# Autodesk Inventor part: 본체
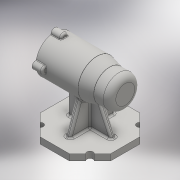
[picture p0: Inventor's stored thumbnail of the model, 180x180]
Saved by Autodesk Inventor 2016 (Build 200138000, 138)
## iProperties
Created: 2019-12
Part Number: 본체
Material: 일반
Document SubType Name: Modeling
Designer: woori
Density: 1 g/cm^3
Appearance: 기본값
Author: woori
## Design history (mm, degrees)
sketch "스케치1"
  geometry: L1 (23.196, 56)-(56, 23.196); L2 (56, 23.196)-(56, -23.196); L3 (56, -23.196)-(23.196, -56); L4 (23.196, -56)-(-23.196, -56); L5 (-23.196, -56)-(-56, -23.196); L6 (-56, -23.196)-(-56, 23.196); L7 (-56, 23.196)-(-23.196, 56); L8 (-23.196, 56)-(23.196, 56); 2 further points
  constraints: 16 end point, 1 coincident, 17 other
  dimensions: "d0" = 56 distance from line of L2 point (0, 0)
extrude "돌출1" new body sketch "스케치1" distance "d1" = 10; taper "d2" = 0 deg
sketch "스케치2"
  geometry: L1 (-56, 80)-(-56, 105); L2 (-56, 105)-(-31, 105); L3 (-31, 105)-(-11, 110); L4 (-11, 110)-(56, 110); L5 (56, 110)-(56, 80); L6 (56, 80)-(-56, 80); L7 (56, 0)-(56, 10) reference; L8 (56, 0)-(23.196, 0) reference; 1 further point
  constraints: 12 end point, 3 perpendicular, 1 collinear, 1 parallel, 1 vertical
  dimensions: "d3" = 45 distance from line of L3.end L1; "d4" = 112 distance between parallel lines of L5 L1; "d5" = 25 distance of L1.end L2.end; "d6" = 60 diameter of L4 L6; "d7" = 50 diameter of L2 L6; "d8" = 80 distance between parallel lines of L8 L6
revolve "회전1" sketch "스케치2" stored, may be unused: angle "d9" = 90 deg
sketch "스케치3"
  geometry: 1 further point
sketch "스케치4"
  geometry: L1 (56, 23.196)-(23.196, 56) reference; L2 (23.196, 56)-(-23.196, 56) reference; L3 (-23.196, 56)-(-56, 23.196) reference; L4 (-56, 23.196)-(-56, -23.196) reference; L5 (-56, -23.196)-(-23.196, -56) reference; L6 (-23.196, -56)-(23.196, -56) reference; L7 (23.196, -56)-(56, -23.196) reference; L8 (56, -23.196)-(56, 23.196) reference; 1 further point
sketch "스케치5"
  geometry: L1 (-23.196, 10)-(-56, 10) reference; L2 (-36, 10)-(-18.979, 56.766); L3 (18.979, 56.766)-(36, 10); L4 (56, 10)-(23.196, 10) reference; L5 (-36, 10)-(36, 10); L6 (23.196, 0)-(56, 0) reference; C1 r 30 at (0, 80); A1 r 30 centre (0, 80) between (-18.979, 56.766) and (18.979, 56.766) reference; 1 further point
  constraints: 6 end point, 2 point on circle, 2 point on line, 1 centre point, 1 coincident, 1 concentric, 1 parallel
  dimensions: "d10" = 20 distance of L1.end L2.start; "d11" = 110 deg angle of L1 L2; "d12" = 20 distance of L4.start L3.end (= d10); "d13" = 110 deg angle of L4 L3
extrude "돌출2" join sketch "스케치5" stored distance "d14" = 8; taper "d15" = 0 deg
sketch "스케치7"
  geometry: L1 (-13.793, 61.912)-(-38, 10); L2 (-56, 10)-(-23.196, 10) reference; L3 (-13.793, 61.912)-(31, 61.912); L4 (31, 61.912)-(31, 10); L5 (23.196, 10)-(56, 10) reference; L6 (-38, 10)-(31, 10); L7 (-23.196, 0)-(23.196, 0) reference; 1 further point
  constraints: 8 end point, 2 point on line, 1 horizontal, 1 parallel, 1 perpendicular
  dimensions: "d21" = 18 distance of L2.start L1.end; "d22" = 25 distance of L5.end L4.end; "d23" = 115 deg angle of L2 L1
extrude "돌출4" join sketch "스케치7" stored distance "d24" = 8; taper "d25" = 0 deg
fillet "모깎기1" dims "d26" = 10
sketch "스케치8"
  geometry: L1 (56, 50)-(56, 110) reference; L2 (56, 80)-(41, 80); L3 (41, 80)-(41, 101); L4 (41, 101)-(56, 101); L5 (56, 101)-(56, 80); L6 (41, 80)-(-13, 80); L7 (-13, 80)-(-13, 104); L8 (-13, 104)-(41, 104); L9 (41, 104)-(41, 80); L10 (-13, 80)-(-25, 80); L11 (-25, 80)-(-25, 101); L12 (-25, 101)-(-13, 101); L13 (-13, 101)-(-13, 80); L14 (-25, 80)-(-43, 80); L15 (-43, 80)-(-43, 97.5); L16 (-43, 97.5)-(-25, 97.5); L17 (-25, 97.5)-(-25, 80); L18 (-43, 80)-(-47, 80); L19 (-47, 80)-(-47, 96); L20 (-47, 96)-(-43, 96); L21 (-43, 96)-(-43, 80); L22 (-47, 80)-(-50, 80); L23 (-50, 80)-(-50, 90.5); L24 (-50, 90.5)-(-47, 90.5); L25 (-47, 90.5)-(-47, 80); 1 further point
  constraints: 48 end point, 12 parallel, 6 horizontal, 6 perpendicular, 1 midpoint
  dimensions: "d27" = 15 distance between parallel lines of L3 L1; "d28" = 54 distance between parallel lines of L3 L13; "d29" = 12 distance between parallel lines of L11 L13; "d30" = 18 distance between parallel lines of L11 L15; "d31" = 3 distance between parallel lines of L19 L23; "d32" = 4 distance between parallel lines of L15 L19; "d33" = 42 diameter of L4 L2; "d34" = 48 diameter of L8 L6; "d35" = 42 diameter of L12 L10; "d36" = 35 diameter of L16 L14; "d37" = 32 diameter of L20 L18; "d38" = 21 diameter of L24 L22
revolve "회전2" sketch "스케치8" stored, may be unused: angle "d39" = 90 deg
fillet "모깎기2" dims "d40" = 0.3
fillet "모깎기3" dims "d41" = 3
fillet "모깎기4" dims "d42" = 3
chamfer "모따기1" distance "d43" = 1; stored, may be unused: second distance "d44" = 2, angle "d45" = 45 deg
sketch "스케치9"
  geometry: L1 (23.196, 56)-(56, 23.196) reference; L2 (56, -23.196)-(23.196, -56) reference; L3 (-23.196, -56)-(-56, -23.196) reference; L4 (-56, 23.196)-(-23.196, 56) reference; C1 r 5 at (39.598, 39.598); C2 r 5 at (39.598, -39.598); C3 r 5 at (-39.598, -39.598); C4 r 5 at (-39.598, 39.598); 2 further points
  constraints: 4 centre point, 4 midpoint, 1 coincident, 3 other
  dimensions: "d46" = 10 diameter of C1; "d47" = 10 diameter of C2 (= d46); "d48" = 10 diameter of C3 (= d46); "d49" = 10 diameter of C4 (= d46)
extrude "돌출5" cut sketch "스케치9" distance "d50" = 10; taper "d51" = 0 deg
sketch "스케치10"
  geometry: C1 r 6 at (30, 0); 2 further points
  constraints: 1 centre point, 1 horizontal alignment, 1 other
  dimensions: "d52" = 12 diameter of C1
extrude "돌출6" join sketch "스케치10" distance "d53" = 16; taper "d54" = 0 deg
fillet "모깎기5" dims "d55" = 3
fillet "모깎기6" dims "d56" = 1
sketch "스케치11"
  geometry: A1 r 6 centre (0, 0) between (0.171, -5.998) and (0.171, 5.998) reference; A2 r 6 centre (-30, 30) between (-24.002, 30.171) and (-35.998, 30.171) reference; A3 r 6 centre (-30, -30) between (-35.998, -30.171) and (-24.002, -30.171) reference; A4 r 3 centre (-60, 0) between (-60.867, 2.872) and (-60.867, -2.872) reference; 5 further points
  constraints: 4 coincident
hole "구멍1" sketch "스케치11" at (0, 0), (-30, -30), (-30, 30), (-60, 0) diameter "d60" = 3.242; stored, may be unused: countersink angle "d64" = 90 deg, drill point angle "d66" = 118 deg; dims "d61" = 8, "d62" = 4, "d63" = 2, "d65" = 11
node "작업 평면1"
sketch "스케치12"
  geometry: L1 (56, 86.771)-(56, 109.226) reference; 2 further points
  constraints: 1 other
  dimensions: "d75" = 41 distance from line of L1 point (15, 80.345)
feature "엠보싱1" sketch "스케치12" dims "d0" = 56, "d8" = 80, "d68" = 0.5, "d69" = 0
fillet "모깎기7" dims "d70" = 1
fillet "모깎기9" dims "d72" = 3
fillet "모깎기10" dims "d73" = 3
fillet "모깎기11" dims "d74" = 3
node "솔리드1"
pattern_circular "원형 패턴1" dims "d58" = 360 deg
